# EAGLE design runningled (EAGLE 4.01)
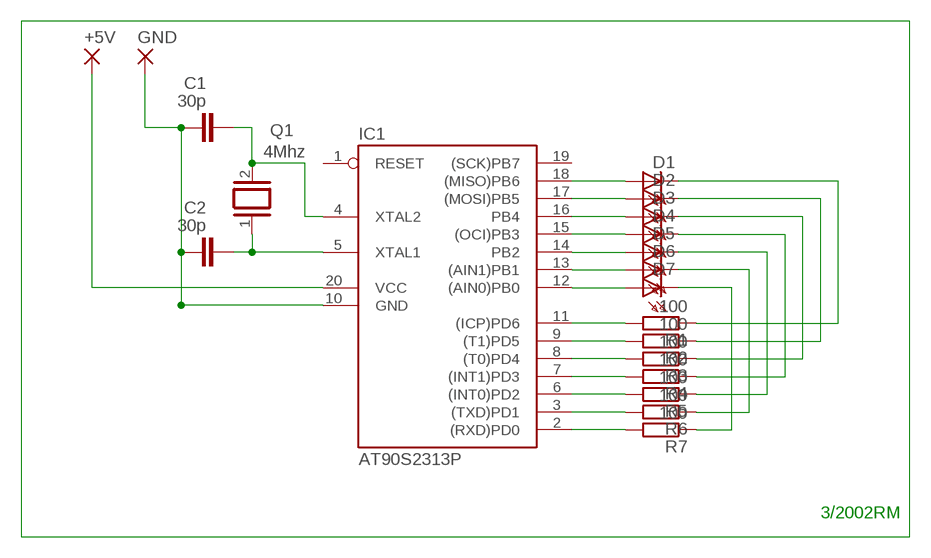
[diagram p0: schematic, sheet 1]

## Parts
+5V  2,15/1,0  [2,15/1,0]
C1  30p  C-EU050-024X044  [C050-024X044]
C2  30p  C-EU050-024X044  [C050-024X044]
D1  LED5MM  [LED5MM]
D2  LED5MM  [LED5MM]
D3  LED5MM  [LED5MM]
D4  LED5MM  [LED5MM]
D5  LED5MM  [LED5MM]
D6  LED5MM  [LED5MM]
D7  LED5MM  [LED5MM]
GND  2,15/1,0  [2,15/1,0]
IC1  AT90S2313P  [DIL20]
Q1  4Mhz  XTAL/S  [QS]
R1  100  R-EU_0204/7  [0204/7]
R2  100  R-EU_0204/7  [0204/7]
R3  100  R-EU_0204/7  [0204/7]
R4  100  R-EU_0204/7  [0204/7]
R5  100  R-EU_0204/7  [0204/7]
R6  100  R-EU_0204/7  [0204/7]
R7  100  R-EU_0204/7  [0204/7]

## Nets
N$1: IC1.2((RXD)PD0) R7.2
N$2: IC1.3((TXD)PD1) R6.2
N$3: IC1.6((INT0)PD2) R5.2
N$4: IC1.7((INT1)PD3) R4.2
N$5: IC1.8((T0)PD4) R3.2
N$6: IC1.9((T1)PD5) R2.2
N$7: IC1.11((ICP)PD6) R1.2
N$8: D6.A IC1.13((AIN1)PB1)
N$9: D7.A IC1.12((AIN0)PB0)
N$10: D5.A IC1.14(PB2)
N$11: D4.A IC1.15((OCI)PB3)
N$12: D3.A IC1.16(PB4)
N$13: D2.A IC1.17((MOSI)PB5)
N$14: D1.A IC1.18((MISO)PB6)
N$15: D7.K(C) R7.1
N$16: D6.K(C) R6.1
N$18: +5V.1(P) IC1.20(VCC)
N$19: D5.K(C) R5.1
N$20: D4.K(C) R4.1
N$21: D3.K(C) R3.1
N$22: D2.K(C) R2.1
N$23: D1.K(C) R1.1
N$24: C2.1 IC1.5(XTAL1) Q1.1
N$25: C1.1 IC1.4(XTAL2) Q1.2
N$26: C1.2 C2.2 GND.1(P) IC1.10(GND)
Unconnected: IC1.1(RESET) IC1.19((SCK)PB7)

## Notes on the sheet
- 3/2002RM

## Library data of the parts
+5V GND = wirepad:2,15/1,0: THROUGH-HOLE PAD
C1 C2 = rcl:C-EU: CAPACITOR, European symbol
D1-D7 = led:LED5MM: LED
IC1 = atmel:AT90S2313: MICROCONTROLLER 2 Kbytes FLASH 128 bytes SRAM 128 bytes EEPROM UART
Q1 = special:XTAL/S: CRYSTAL
R1-R7 = rcl:R-EU_: RESISTOR, European symbol

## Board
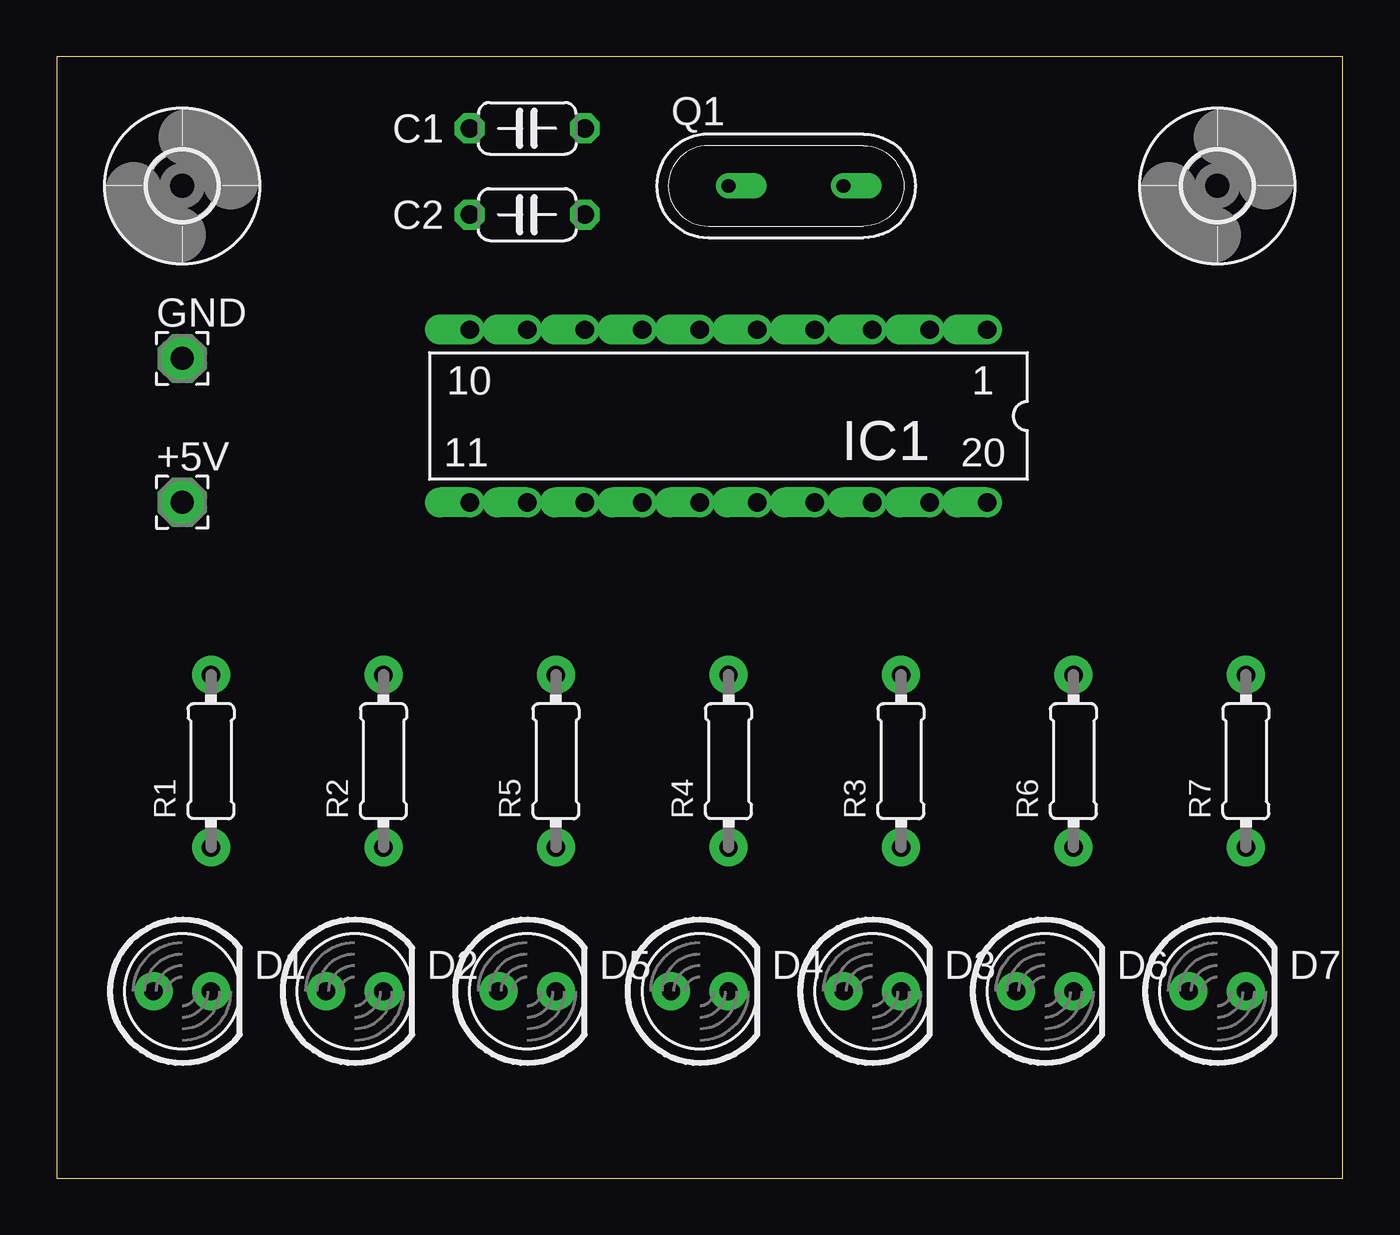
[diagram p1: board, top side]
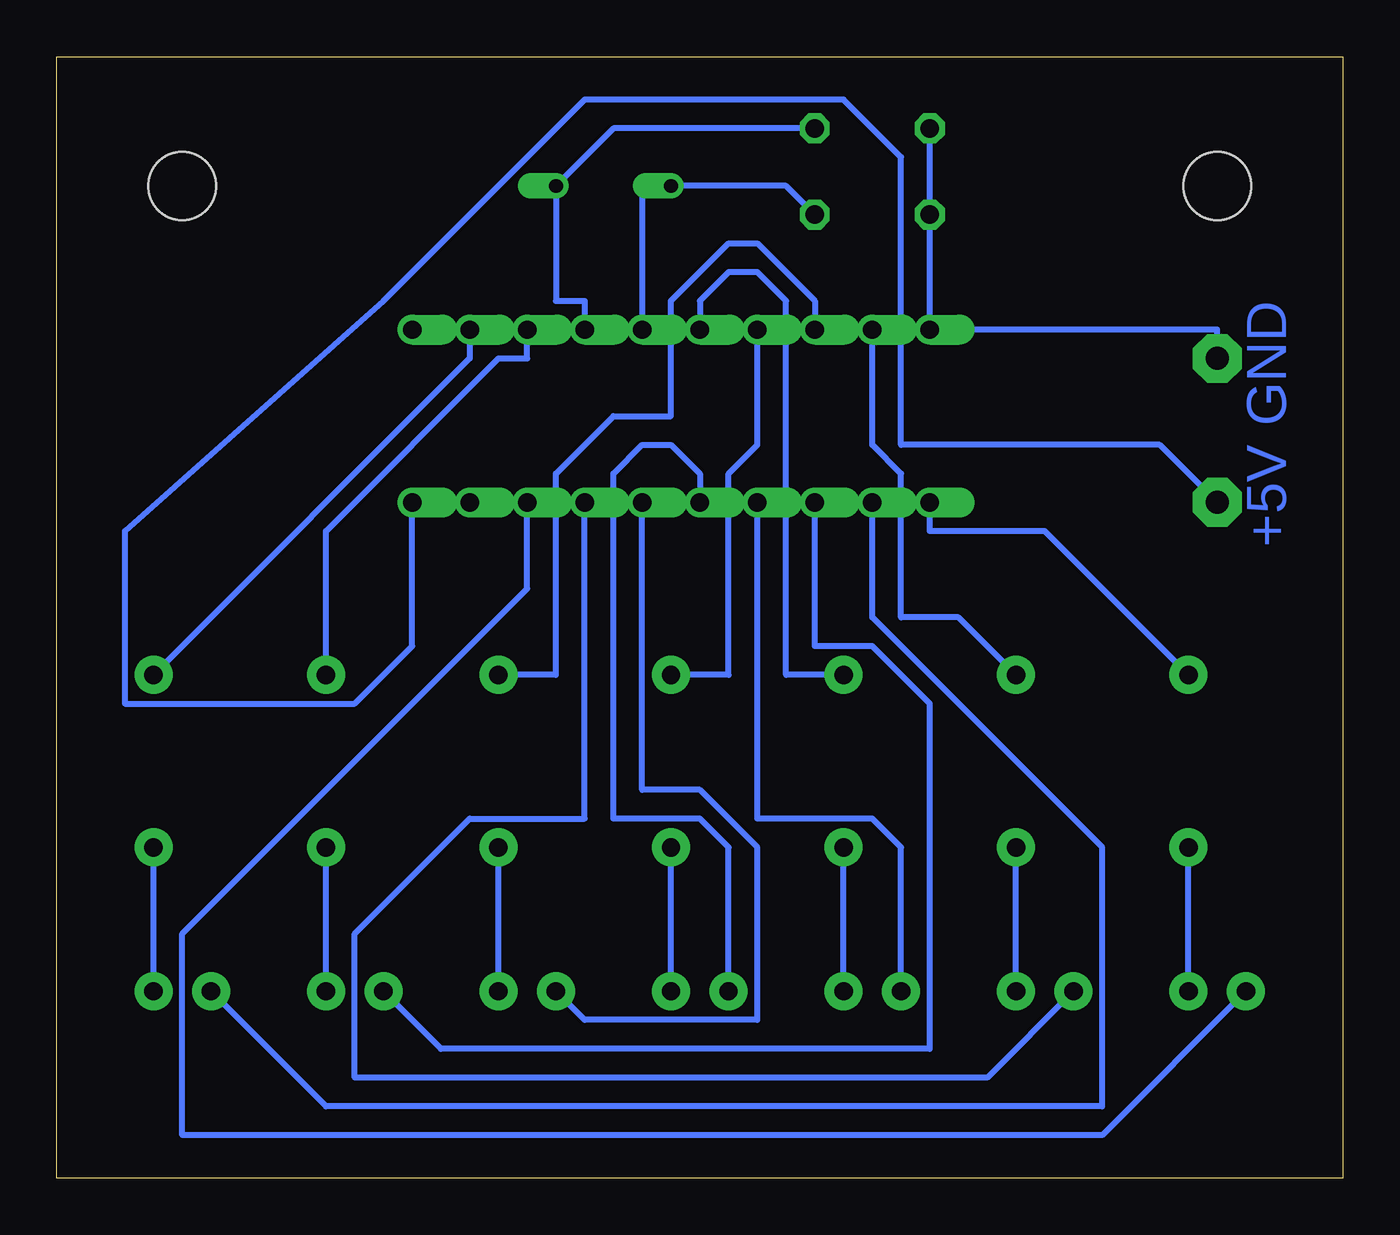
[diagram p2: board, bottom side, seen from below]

Size 56.82 x 49.52 mm. Coordinates in mm from the lower left corner, seen from the top.
Outline: 0,0 56.82,0 56.82,49.52 0,49.52 0,0
Copper layers used: Bottom

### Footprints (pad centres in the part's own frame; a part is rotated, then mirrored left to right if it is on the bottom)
2,15/1,0 = drill 1.016 pad 2.159 octagon: 1 0,0
C050-024X044 = drill 0.813 octagon: 1 -2.54,0; 2 2.54,0
LED5MM = drill 0.813 pad 1.676 round: A -1.27,0; K 1.27,0
DIL20 = drill 0.813 offset: 1 -11.43,-3.81; 2 -8.89,-3.81; 3 -6.35,-3.81; 4 -3.81,-3.81; 5 -1.27,-3.81; 6 1.27,-3.81; 7 3.81,-3.81; 8 6.35,-3.81; 9 8.89,-3.81; 10 11.43,-3.81; 11 11.43,3.81; 12 8.89,3.81; 13 6.35,3.81; 14 3.81,3.81; 15 1.27,3.81; 16 -1.27,3.81; 17 -3.81,3.81; 18 -6.35,3.81; 19 -8.89,3.81; 20 -11.43,3.81
QS = drill 0.61 offset: 1 -2.54,0; 2 2.54,0
0204/7 = drill 0.813 pad 1.676 round: 1 -3.81,0; 2 3.81,0
3,0 = hole 3: 0,0

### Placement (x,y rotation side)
+5V  5.55,29.84 0 top
C1  20.79,46.35 180 top
C2  20.79,42.54 180 top
D1  5.55,8.25 0 top
D2  13.17,8.25 0 top
D3  36.03,8.25 0 top
D4  28.41,8.25 0 top
D5  20.79,8.25 0 top
D6  43.65,8.25 0 top
D7  51.27,8.25 0 top
GND  5.55,36.19 0 top
IC1  29.68,33.65 180 top
Q1  32.22,43.81 0 top
R1  6.82,18.41 90 top
R2  14.44,18.41 90 top
R3  37.3,18.41 90 top
R4  29.68,18.41 90 top
R5  22.06,18.41 90 top
R6  44.92,18.41 90 top
R7  52.54,18.41 90 top
U$1  [3,0]  5.55,43.81 0 top
U$2  [3,0]  51.27,43.81 0 top

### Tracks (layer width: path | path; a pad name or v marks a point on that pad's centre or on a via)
N$1
  Bottom 0.254: R7.2 38.57,36.19 IC1.2
N$2
  Bottom 0.254: R6.2 44.92,28.57 37.3,36.19 36.03,36.19 IC1.3
N$3
  Bottom 0.254: R5.2 24.6,22.22 24.6,38.73 25.87,40 27.14,40 28.41,38.73 IC1.6
N$4
  Bottom 0.254: R4.2 27.14,22.22 27.14,31.11 25.87,32.38 IC1.7
N$5
  Bottom 0.254: R3.2 34.76,22.22 34.76,31.11 32.22,33.65 29.68,33.65 29.68,38.73 27.14,41.27 25.87,41.27 23.33,38.73 IC1.8
N$6
  Bottom 0.254: R2.2 16.98,24.76 19.52,24.76 19.52,31.11 20.79,32.38 IC1.9
N$7
  Bottom 0.254: R1.2 13.17,28.57 18.25,28.57 IC1.11
N$8
  Bottom 0.254: D6.A 39.84,5.71 18.25,5.71 18.25,20.95 20.79,23.49 23.33,23.49 IC1.13
N$9
  Bottom 0.254: D7.A 44.92,3.17 10.63,3.17 10.63,14.6 20.79,24.76 IC1.12
N$10
  Bottom 0.254: D5.A 19.52,14.6 20.79,15.87 25.87,15.87 IC1.14
N$11
  Bottom 0.254: D4.A 27.14,14.6 28.41,15.87 32.22,15.87 32.22,31.11 30.95,32.38 29.68,32.38 28.41,31.11 IC1.15
N$12
  Bottom 0.254: D3.A 33.49,6.98 25.87,6.98 25.87,14.6 28.41,17.14 30.95,17.14 IC1.16
N$13
  Bottom 0.254: D2.A 15.71,4.44 43.65,4.44 43.65,10.79 38.57,15.87 33.49,15.87 IC1.17
N$14
  Bottom 0.254: D1.A 10.63,1.9 51.27,1.9 51.27,10.79 36.03,26.03 IC1.18
N$15
  Bottom 0.254: D7.K R7.1
N$16
  Bottom 0.254: D6.K R6.1
N$18
  Bottom 0.254: +5V.1 8.09,32.38 19.52,32.38 19.52,45.08 22.06,47.62 33.49,47.62 42.38,38.73 53.81,28.57 53.81,20.95 43.65,20.95 41.11,23.49 IC1.20
N$19
  Bottom 0.254: D5.K R5.1
N$20
  Bottom 0.254: D4.K R4.1
N$21
  Bottom 0.254: D3.K R3.1
N$22
  Bottom 0.254: D2.K R2.1
N$23
  Bottom 0.254: D1.K R1.1
N$24
  Bottom 0.254: C2.1 24.6,43.81 Q1.1 30.95,43.81 IC1.5
N$25
  Bottom 0.254: IC1.4 33.49,38.73 34.76,38.73 Q1.2 32.22,46.35 C1.1
N$26
  Bottom 0.254: C1.2 C2.2 IC1.10 5.55,37.46 GND.1

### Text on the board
Bottom: GND | +5V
